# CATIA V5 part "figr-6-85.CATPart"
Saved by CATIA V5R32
Part number: Part1
Bounding box of the stored display mesh (mm): x -164.957 to 164.957, y -91.653 to 91.653, z 0 to 73.378
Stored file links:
  D:\PROJECTS\Project 2022\CATIA V5 6R 2022\Resources\Part Files\c06_catia_v5_6r2022_prt\figr-6-85.CATPart
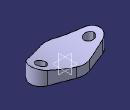
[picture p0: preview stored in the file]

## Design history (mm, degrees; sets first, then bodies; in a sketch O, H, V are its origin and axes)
Body1 (main body)
  Sketch1 on xy-plane, origin (0, 0, 0), H (1, 0, 0), V (0, 1, 0)
    arc A1 centre (0, 0) radius 91.6528 from (-32.9557, -85.5228) to (32.9557, -85.5228) ccw
    point P1 (0, 91.6528)
    arc A2 centre (-114.4606, 0) radius 50.4961 from (-132.6175, 47.1188) to (-132.6175, -47.1188) ccw
    point P2 (-114.4606, 0)
    arc A3 centre (114.4606, 0) radius 50.4961 from (132.6175, 47.1188) to (132.6175, -47.1188) cw
    line L1 (-132.6175, 47.1188) -> (-32.9557, 85.5228)
    point P4 (-132.6175, 47.1188)
    point P5 (-32.9557, 85.5228)
    line L2 (-132.6175, -47.1188) -> (-32.9557, -85.5228)
    point P6 (-132.6175, -47.1188)
    point P7 (-32.9557, -85.5228)
    point P8 (32.9557, -85.5228)
    point P9 (132.6175, -47.1188)
    line L3 (132.6175, -47.1188) -> (32.9557, -85.5228)
    point P10 (32.9557, 85.5228)
    point P11 (132.6175, 47.1188)
    line L4 (132.6175, 47.1188) -> (32.9557, 85.5228)
    point P12 (-32.9557, -85.5228)
    point P13 (32.9557, -85.5228)
    arc A4 centre (0, 0) radius 91.6528 from (32.9557, 85.5228) to (-32.9557, 85.5228) ccw
    circle A5 centre (-114.4606, 0) radius 22.8078
    circle A6 centre (114.4606, 0) radius 22.8078
    coincidence: A1 P1, P1 V, P2 H, P7 A1, L2 P12, L3 P13, A1 A4, P7 P12, P8 P13
    symmetry: A2 A3 V, P7 P8 V, P6 P9 V, L2 L3 V, P5 P10 V, P4 P11 V, L1 L4 V
    tangency: L1 A1, L1 A2, A2 L2, A1 L2, L3 A1, A5 A1, A6 A1
  Pad1: profile Sketch1, direction (0, 0, 1), length 87
  Sketch2 on zx-plane, origin (0, 0, 0), H (-1, 0, 0), V (0, 0, 1)
    spline S1 through (-270.5707, 119.9036) (-20.9781, 45.6362) (270.425, 111.0056)
  Extrude1: Element1 Sketch2, Lim1 -147, Lim2 -147
  Align1: SewingRemoveFace end face of Pad1, SplitPlane Extrude1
